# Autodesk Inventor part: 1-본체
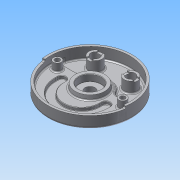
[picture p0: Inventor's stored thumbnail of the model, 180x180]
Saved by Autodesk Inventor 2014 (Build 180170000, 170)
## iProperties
Created: 2015-06
Part Number: 1-본체
Material: 알루미늄 6061
Document SubType Name: Modeling
Designer: Administrator
Density: 2.71 g/cm^3
Appearance: 알루미늄 - 평지
Mass: 1071.11 g
Surface Area: 1034.48 cm^2
Volume: 395.243 cm^3
Author: Administrator
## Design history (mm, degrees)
sketch "스케치1"
  geometry: C1 r 95 at (0, 0); 1 further point
  constraints: 1 centre point, 1 coincident
  dimensions: "d0" = 190 diameter of C1
extrude "돌출1" new body sketch "스케치1" distance "d1" = 32; taper "d2" = 0 deg
sketch "스케치2"
  geometry: C1 r 95 at (0, 0) reference; C2 r 90 at (0, 0)
  constraints: 1 centre point, 1 coincident
  dimensions: "d3" = 180 diameter of C2
extrude "돌출2" cut sketch "스케치2" distance "d4" = 18; taper "d5" = 0 deg
sketch "스케치3"
  geometry: L1 (-88.566, 16)-(88.566, 16); A1 r 90 centre (0, 0) between (-88.566, 16) and (88.566, 16) reference; A2 r 90 centre (0, 0) between (88.566, 16) and (-88.566, 16); A3 r 42 centre (0, 0) between (38.833, 16) and (-38.833, 16)
  constraints: 6 point on circle, 2 centre point, 2 end point, 2 point on line, 1 coincident, 1 concentric, 1 horizontal
  dimensions: "d6" = 16 distance from line of L1 A1.centre; "d7" = 84 diameter of A3
extrude "돌출3" cut sketch "스케치3" distance "d8" = 7; taper "d9" = 0 deg
sketch "스케치4"
  geometry: C1 r 35 at (0, 0); A1 r 42 centre (0, 0) between (38.833, 16) and (-38.833, 16) reference
  constraints: 1 centre point, 1 coincident
  dimensions: "d10" = 70 diameter of C1
extrude "돌출4" join sketch "스케치4" distance "d11" = 10; taper "d12" = -10 deg
sketch "스케치5"
  geometry: L1 (88.566, 16)-(38.833, 16) reference; L2 (-87.972, -19)-(87.972, -19); L3 (0, 0)-(0, -90); L4 (-88.904, -14)-(88.904, -14); L5 (-59, -19)-(-59, -14); L6 (-41, -19)-(-41, -14); L7 (41, -19)-(41, -14); L8 (59, -19)-(59, -14); C1 r 35 at (0, 0) reference; A1 r 90 centre (0, 0) between (-88.566, 16) and (88.566, 16) reference; A2 r 42 centre (0, 0) between (38.833, 16) and (-38.833, 16) reference; A3 r 41 centre (0, -19) between (-41, -19) and (41, -19); A4 r 59 centre (0, -19) between (-59, -19) and (59, -19); A5 r 9 centre (-50, -14) between (-41, -14) and (-59, -14); A6 r 9 centre (50, -14) between (59, -14) and (41, -14)
  constraints: 14 end point, 13 point on circle, 9 point on line, 8 tangent, 4 centre point, 4 perpendicular, 3 parallel, 1 coincident, 1 midpoint
  dimensions: "d13" = 19 distance from line of L2 C1.centre; "d16" = 5 distance between parallel lines of L4 L2; "d17" = 59 radius of A4; "d18" = 41 radius of A3
extrude "돌출5" cut sketch "스케치5" distance "d19" = 7; taper "d20" = 0 deg
sketch "스케치7"
  geometry: L1 (-95, 0)-(95, 0); L2 (-89.124, -12.526)-(-94.075, -13.221); L3 (89.124, -12.526)-(94.075, -13.221); C1 r 95 at (0, 0) reference; A1 r 90 centre (0, 0) between (-89.124, -12.526) and (89.124, -12.526); A2 r 95 centre (0, 0) between (-94.075, -13.221) and (94.075, -13.221); 2 further points
  constraints: 6 end point, 4 point on circle, 2 centre point, 2 coincident, 1 horizontal, 2 other
  dimensions: "d28" = 190 distance of L1.start L1.end; "d29" = 8 deg angle of L2 L1; "d30" = 8 deg angle of L3 L1; "d31" = 95 radius of A2; "d32" = 0 distance from line of point (0, 0) L3; "d33" = 0 distance from line of point (0, 0) L1; "d34" = 0 distance from line of point (0, 0) L2; "d35" = 13.22144 distance from line of L1.end L3
extrude "돌출6" cut sketch "스케치7" distance "d36" = 5; taper "d37" = 0 deg
sketch "스케치8"
  geometry: C1 r 95 at (0, 0) reference; C2 r 15 at (40, 52); C3 r 15 at (-40, 52)
  constraints: 2 centre point, 1 horizontal alignment
  dimensions: "d43" = 30 diameter of C3; "d44" = 30 diameter of C2; "d45" = 80 distance of C3.centre C2.centre; "d46" = 40 horizontal distance of C1.centre C2.centre; "d47" = 52 vertical distance of C1.centre C2.centre
extrude "돌출7" join sketch "스케치8" stored distance "d48" = 7; taper "d49" = 0 deg
sketch "스케치9"
  geometry: C1 r 15 at (0, 0) reference; C2 r 15 at (80, 0) reference; 3 further points
  constraints: 2 coincident
hole "구멍1" sketch "스케치9" at (0, 0), (80, 0) diameter "d50" = 20; stored, may be unused: countersink angle "d54" = 90 deg, drill point angle "d56" = 118 deg; dims "d51" = 6, "d52" = 4, "d53" = 2, "d55" = 8
sketch "스케치10"
  geometry: L1 (6, -19.376)-(-6, -19.376); L2 (-6, -19.376)-(-6, 19.376); L3 (-6, 19.376)-(6, 19.376); L4 (6, 19.376)-(6, -19.376); L5 (6, -19.376)-(-6, 19.376); L6 (-6, -19.376)-(6, 19.376); L7 (59.502, 6)-(100.498, 6); L8 (100.498, 6)-(100.498, -6); L9 (100.498, -6)-(59.502, -6); L10 (59.502, -6)-(59.502, 6); L11 (59.502, 6)-(100.498, -6); L12 (100.498, 6)-(59.502, -6); C1 r 15 at (0, 0) reference; C2 r 10 at (80, 0) reference; C3 r 15 at (80, 0) reference; 3 further points
  constraints: 24 end point, 5 midpoint, 4 parallel, 2 horizontal, 2 perpendicular, 1 coincident
  dimensions: "d57" = 12 distance of L2.end L3.end; "d58" = 12 distance of L9.end L7.start; "d59" = 38.75256 distance of L3.end L1.start; "d60" = 40.99632 distance of L8.end L9.end
extrude "돌출8" cut sketch "스케치10" distance "d61" = 3; taper "d62" = 0 deg
sketch "스케치13"
  geometry: C1 r 95 at (0, 0) reference; C2 r 26 at (0, 0)
  constraints: 1 centre point, 1 coincident
  dimensions: "d71" = 52 diameter of C2
extrude "돌출9" join sketch "스케치13" distance "d72" = 12; taper "d73" = -15 deg
sketch "스케치14"
  geometry: C1 r 33.237 at (0, 0) reference; 1 further point
  constraints: 1 coincident
hole "구멍3" sketch "스케치14" at (0, 0) diameter "d74" = 23; stored, may be unused: countersink angle "d78" = 90 deg, drill point angle "d80" = 118 deg; dims "d75" = 6, "d76" = 50, "d77" = 15, "d79" = 8
sketch "스케치16"
  geometry: L1 (88.566, 16)-(38.833, 16) reference; L2 (-90, 0)-(90, 0); C1 r 9 at (-74, 0); C2 r 9 at (74, 0); A1 r 90 centre (0, 0) between (-88.566, 16) and (88.566, 16) reference; A2 r 42 centre (0, 0) between (38.833, 16) and (-38.833, 16) reference; A3 r 74 centre (0, 0) between (-74, 0) and (74, 0)
  constraints: 4 point on circle, 3 centre point, 2 end point, 2 point on line, 1 coincident, 1 parallel
  dimensions: "d83" = 180 distance of L2.start L2.end; "d84" = 148 diameter of A3; "d85" = 18 diameter of C2; "d86" = 18 diameter of C1
extrude "돌출10" join sketch "스케치16" stored distance "d87" = 12; taper "d88" = 0 deg
sketch "스케치17"
  geometry: C1 r 9 at (-74, 0) reference; C2 r 9 at (74, 0) reference; 2 further points
  constraints: 2 coincident
hole "구멍4" sketch "스케치17" at (-74, 0), (74, 0) diameter "d89" = 11; stored, may be unused: countersink angle "d93" = 90 deg, drill point angle "d95" = 118 deg; dims "d90" = 6, "d91" = 18, "d92" = 11, "d94" = 8
fillet "모깎기1" dims "d96" = 10
fillet "모깎기2" dims "d97" = 3
fillet "모깎기3" dims "d98" = 3
fillet "모깎기4" dims "d99" = 3
fillet "모깎기5" dims "d100" = 3
fillet "모깎기6" dims "d101" = 3
chamfer "모따기1" distance "d102" = 1; stored, may be unused: second distance "d103" = 2, angle "d104" = 45 deg
fillet "모깎기7" dims "d105" = 0.3
fillet "모깎기8" dims "d106" = 1
chamfer "모따기2" distance "d107" = 1; stored, may be unused: second distance "d108" = 2, angle "d109" = 45 deg
sketch "스케치19"
  geometry: C1 r 95 at (0, 0) reference; C2 r 68 at (0, 0)
  constraints: 1 centre point, 1 coincident, 1 other
  dimensions: "d110" = 136 diameter of C2
feature "엠보싱1" sketch "스케치19" dims "d111" = 0.5, "d112" = 0
fillet "모깎기10" dims "d114" = 3
chamfer "모따기3" distance "d115" = 1; stored, may be unused: second distance "d116" = 2, angle "d117" = 45 deg
fillet "모깎기11" dims "d118" = 3
fillet "모깎기12" dims "d119" = 5
fillet "모깎기13" dims "d120" = 3
node "솔리드1"
node "투영된 루프1"
other parameters: "d14" = 59, "d15" = 41
